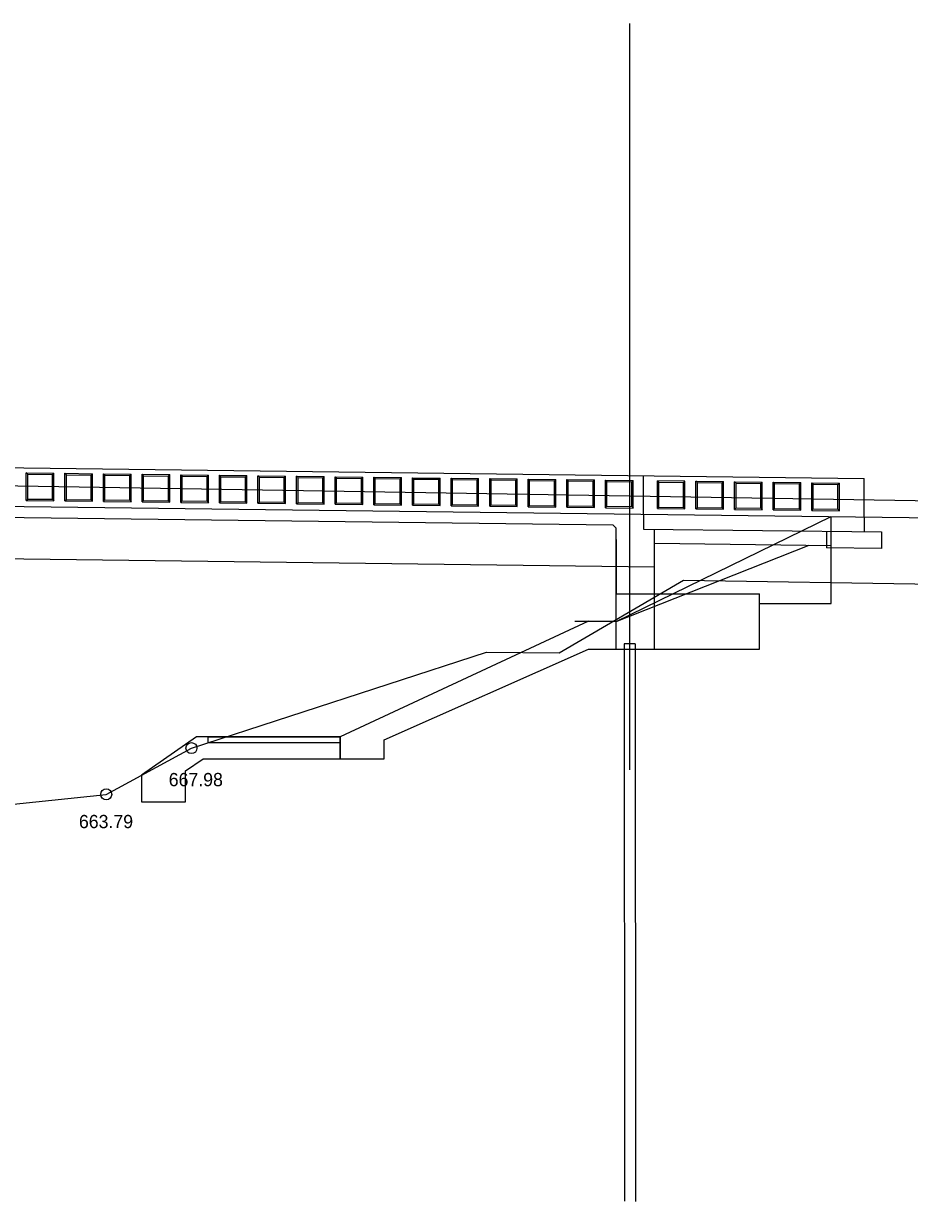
# Model space of a CAD drawing. Extents: x -845213 to 599959, y -257022 to 228999.
# Drawn here: x 595643.5 to 595723.8, y 228653.8 to 228760.5 of the extents above; entities that cross this region are included whole.
import ezdxf

# ---------------------------------------------------------------- set-up
doc = ezdxf.new("R2010")
doc.units = 0
for name, color, linetype in [('B_CL', 7, 'Continuous'), ('B_CONC', 7, 'Continuous'), ('B_CONC_HIDDEN', 7, 'Continuous'), ('B_CONST', 7, 'Continuous'), ('B_GROUNDLINE', 7, 'Continuous'), ('B_MISC', 7, 'Continuous'), ('B_PATTERN', 7, 'Continuous'), ('B_PILES_HIDDEN', 7, 'Continuous'), ('B_PROP', 7, 'Continuous'), ('B_SCREEN', 7, 'Continuous'), ('E_STRUCT', 7, 'Continuous'), ('P_E_PROF', 7, 'Continuous'), ('P_PROF', 7, 'Continuous')]:
    doc.layers.add(name, color=color, linetype=linetype)

msp = doc.modelspace()

# ---------------------------------------------------------------- linework, layer by layer
at = {"layer": 'B_CL'}
for p, q in [((595698.5, 228692.87), (595698.5, 228760.49)), ((595698.5, 228703.82), (595698.5, 228708.82))]:
    msp.add_line(p, q, dxfattribs=at)
at = {"layer": 'B_CONC'}
for p, q in [((595399.25, 228723.31), (595719.75, 228719.29)), ((595699.75, 228716.04), (595699.75, 228719.54)), ((595719.75, 228715.79), (595719.75, 228719.29)), ((595421.62, 228718.53), (595696.95, 228715.07)), ((595716.75, 228707.95), (595716.75, 228715.83)), ((595417.81, 228714.82), (595700.75, 228711.28)), ((595697.25, 228714.77), (595696.95, 228715.07)), ((595697.25, 228703.82), (595697.25, 228714.77)), ((595710.25, 228703.82), (595710.25, 228708.82)), ((595710.25, 228707.95), (595716.75, 228707.95))]:
    msp.add_line(p, q, dxfattribs=at)
at = {"layer": 'B_CONC_HIDDEN'}
msp.add_line((595699.75, 228716.04), (595699.75, 228715.04), dxfattribs=at)
at = {"layer": 'B_CONST'}
for p, q in [((595697.25, 228713.75), (595697.25, 228708.84)), ((595697.25, 228706.51), (595697.25, 228711.51))]:
    msp.add_line(p, q, dxfattribs=at)
at = {"layer": 'B_GROUNDLINE'}
msp.add_lwpolyline([(595697.25, 228706.32), (595716.75, 228715.83)], dxfattribs=at)
at = {"layer": 'B_MISC'}
for p, q in [((595697.25, 228706.32), (595714.75, 228713.23)), ((595700.75, 228703.82), (595700.75, 228713.43)), ((595700.75, 228713.43), (595716.75, 228713.2)), ((595716.75, 228707.95), (595716.75, 228713.2)), ((595697.25, 228703.82), (595697.25, 228708.82)), ((595697.25, 228708.82), (595710.25, 228708.82)), ((595710.25, 228703.82), (595710.25, 228708.82)), ((595710.25, 228707.95), (595716.75, 228707.95)), ((595697.25, 228706.32), (595693.53, 228706.32)), ((595697.25, 228703.82), (595697.25, 228706.42)), ((595697.25, 228703.82), (595710.25, 228703.82))]:
    msp.add_line(p, q, dxfattribs=at)
for centre in [(595658.77, 228694.85), (595651.04, 228690.66)]:
    msp.add_circle(centre, 0.5, dxfattribs=at)
at = {"layer": 'B_PATTERN'}
for points in [[(595697.25, 228703.82), (595697.25, 228706.32), (595694.75, 228706.35), (595672.25, 228695.87), (595672.25, 228693.87), (595676.25, 228693.87), (595676.25, 228695.61), (595694.75, 228703.82)], [(595672.25, 228693.87), (595672.25, 228695.87), (595659.24, 228695.86), (595654.24, 228692.41), (595654.24, 228689.99), (595658.24, 228689.99), (595658.24, 228692.78), (595659.84, 228693.87)]]:
    msp.add_lwpolyline(points, close=True, dxfattribs=at)
at = {"layer": 'B_PILES_HIDDEN'}
for p, q in [((595699, 228704.29), (595698, 228704.31)), ((595698, 228704.31), (595698.02, 228653.8)), ((595699, 228704.29), (595699.02, 228653.78))]:
    msp.add_line(p, q, dxfattribs=at)
at = {"layer": 'B_PROP'}
for p, q in [((595660.25, 228695.87), (595672.25, 228695.87)), ((595660.25, 228695.87), (595660.25, 228695.37)), ((595660.25, 228695.37), (595672.25, 228695.37))]:
    msp.add_line(p, q, dxfattribs=at)
at = {"layer": 'B_SCREEN'}
for p, q in [((595643.8, 228717.29), (595643.8, 228719.79)), ((595643.8, 228719.79), (595646.3, 228719.76)), ((595643.93, 228719.66), (595643.8, 228719.79)), ((595643.93, 228719.66), (595646.18, 228719.64)), ((595643.93, 228717.41), (595643.93, 228719.66)), ((595646.18, 228719.64), (595646.3, 228719.76)), ((595646.18, 228717.39), (595646.18, 228719.64)), ((595646.3, 228717.26), (595646.3, 228719.76)), ((595647.3, 228717.25), (595647.3, 228719.75)), ((595647.3, 228719.75), (595649.8, 228719.71)), ((595647.43, 228719.62), (595647.3, 228719.75)), ((595647.43, 228719.62), (595649.68, 228719.59)), ((595647.43, 228717.37), (595647.43, 228719.62)), ((595649.68, 228719.59), (595649.8, 228719.71)), ((595649.68, 228717.34), (595649.68, 228719.59)), ((595649.8, 228717.21), (595649.8, 228719.71)), ((595650.8, 228717.2), (595650.8, 228719.7)), ((595650.8, 228719.7), (595653.3, 228719.67)), ((595650.93, 228719.58), (595650.8, 228719.7)), ((595650.93, 228719.58), (595653.18, 228719.55)), ((595650.93, 228717.33), (595650.93, 228719.58)), ((595653.18, 228719.55), (595653.3, 228719.67)), ((595653.18, 228717.3), (595653.18, 228719.55)), ((595653.3, 228717.17), (595653.3, 228719.67)), ((595654.3, 228717.16), (595654.3, 228719.66)), ((595654.3, 228719.66), (595656.8, 228719.63)), ((595654.43, 228719.53), (595654.3, 228719.66)), ((595654.43, 228719.53), (595656.68, 228719.5)), ((595654.43, 228717.28), (595654.43, 228719.53)), ((595656.68, 228719.5), (595656.8, 228719.63)), ((595656.68, 228717.25), (595656.68, 228719.5)), ((595656.8, 228717.13), (595656.8, 228719.63)), ((595657.8, 228717.11), (595657.8, 228719.61)), ((595657.8, 228719.61), (595660.3, 228719.58)), ((595657.93, 228719.49), (595657.8, 228719.61)), ((595657.93, 228719.49), (595660.18, 228719.46)), ((595657.93, 228717.24), (595657.93, 228719.49)), ((595660.18, 228719.46), (595660.3, 228719.58)), ((595660.18, 228717.21), (595660.18, 228719.46)), ((595660.3, 228717.08), (595660.3, 228719.58)), ((595661.3, 228717.07), (595661.3, 228719.57)), ((595661.3, 228719.57), (595663.8, 228719.54)), ((595661.43, 228719.44), (595661.3, 228719.57)), ((595661.43, 228719.44), (595663.68, 228719.42)), ((595661.43, 228717.19), (595661.43, 228719.44)), ((595663.68, 228719.42), (595663.8, 228719.54)), ((595663.68, 228717.17), (595663.68, 228719.42)), ((595663.8, 228717.04), (595663.8, 228719.54)), ((595664.8, 228717.03), (595664.8, 228719.53)), ((595664.8, 228719.53), (595667.3, 228719.5)), ((595664.93, 228719.4), (595664.8, 228719.53)), ((595664.93, 228719.4), (595667.18, 228719.37)), ((595664.93, 228717.15), (595664.93, 228719.4)), ((595667.18, 228719.37), (595667.3, 228719.5)), ((595667.18, 228717.12), (595667.18, 228719.37)), ((595667.3, 228717), (595667.3, 228719.5)), ((595668.3, 228716.98), (595668.3, 228719.48)), ((595668.3, 228719.48), (595670.8, 228719.45)), ((595668.43, 228719.36), (595668.3, 228719.48)), ((595668.43, 228719.36), (595670.68, 228719.33)), ((595668.43, 228717.11), (595668.43, 228719.36)), ((595670.68, 228719.33), (595670.8, 228719.45)), ((595670.68, 228717.08), (595670.68, 228719.33)), ((595670.8, 228716.95), (595670.8, 228719.45)), ((595671.8, 228716.94), (595671.8, 228719.44)), ((595671.8, 228719.44), (595674.3, 228719.41)), ((595671.93, 228719.31), (595671.8, 228719.44)), ((595671.93, 228719.31), (595674.18, 228719.28)), ((595671.93, 228717.06), (595671.93, 228719.31)), ((595674.18, 228719.28), (595674.3, 228719.41)), ((595674.18, 228717.03), (595674.18, 228719.28)), ((595674.3, 228716.91), (595674.3, 228719.41)), ((595675.3, 228716.9), (595675.3, 228719.39)), ((595675.3, 228719.39), (595677.8, 228719.36)), ((595675.43, 228719.27), (595675.3, 228719.39)), ((595675.43, 228719.27), (595677.68, 228719.24)), ((595675.43, 228717.02), (595675.43, 228719.27)), ((595677.68, 228719.24), (595677.8, 228719.36)), ((595677.68, 228716.99), (595677.68, 228719.24)), ((595677.8, 228716.86), (595677.8, 228719.36)), ((595678.8, 228716.85), (595678.8, 228719.35)), ((595678.8, 228719.35), (595681.3, 228719.32)), ((595678.93, 228719.22), (595678.8, 228719.35)), ((595678.93, 228719.22), (595681.18, 228719.2)), ((595678.93, 228716.97), (595678.93, 228719.22)), ((595681.18, 228719.2), (595681.3, 228719.32)), ((595681.18, 228716.95), (595681.18, 228719.2)), ((595681.3, 228716.82), (595681.3, 228719.32)), ((595682.3, 228716.81), (595682.3, 228719.31)), ((595682.3, 228719.31), (595684.8, 228719.28)), ((595682.43, 228719.18), (595682.3, 228719.31)), ((595682.43, 228719.18), (595684.67, 228719.15)), ((595682.43, 228716.93), (595682.43, 228719.18)), ((595684.67, 228719.15), (595684.8, 228719.28)), ((595684.67, 228716.9), (595684.67, 228719.15)), ((595684.8, 228716.78), (595684.8, 228719.28)), ((595685.8, 228716.76), (595685.8, 228719.26)), ((595685.8, 228719.26), (595688.3, 228719.23)), ((595685.92, 228719.14), (595685.8, 228719.26)), ((595685.92, 228719.14), (595688.17, 228719.11)), ((595685.92, 228716.89), (595685.92, 228719.14)), ((595688.17, 228719.11), (595688.3, 228719.23)), ((595688.17, 228716.86), (595688.17, 228719.11)), ((595688.3, 228716.73), (595688.3, 228719.23)), ((595689.3, 228716.72), (595689.3, 228719.22)), ((595689.3, 228719.22), (595691.8, 228719.19)), ((595689.42, 228719.09), (595689.3, 228719.22)), ((595689.42, 228719.09), (595691.67, 228719.06)), ((595689.42, 228716.84), (595689.42, 228719.09)), ((595691.67, 228719.06), (595691.8, 228719.19)), ((595691.67, 228716.81), (595691.67, 228719.06)), ((595691.8, 228716.69), (595691.8, 228719.19)), ((595692.8, 228716.68), (595692.8, 228719.18)), ((595692.8, 228719.18), (595695.3, 228719.14)), ((595692.92, 228719.05), (595692.8, 228719.18)), ((595692.92, 228719.05), (595695.17, 228719.02)), ((595692.92, 228716.8), (595692.92, 228719.05)), ((595695.17, 228719.02), (595695.3, 228719.14)), ((595695.17, 228716.77), (595695.17, 228719.02)), ((595695.3, 228716.64), (595695.3, 228719.14)), ((595696.3, 228716.63), (595696.3, 228719.13)), ((595696.3, 228719.13), (595698.8, 228719.1)), ((595696.42, 228719.01), (595696.3, 228719.13)), ((595696.42, 228719.01), (595698.67, 228718.98)), ((595696.42, 228716.76), (595696.42, 228719.01)), ((595698.67, 228718.98), (595698.8, 228719.1)), ((595698.67, 228716.73), (595698.67, 228718.98)), ((595698.8, 228716.6), (595698.8, 228719.1)), ((595703.5, 228719.04), (595701, 228719.07)), ((595701, 228716.57), (595701, 228719.07)), ((595701.13, 228718.94), (595701, 228719.07)), ((595701.13, 228718.94), (595703.38, 228718.91)), ((595701.13, 228716.69), (595701.13, 228718.94)), ((595703.38, 228718.91), (595703.5, 228719.04)), ((595703.38, 228716.66), (595703.38, 228718.91)), ((595703.5, 228716.54), (595703.5, 228719.04)), ((595704.5, 228716.53), (595704.5, 228719.03)), ((595704.5, 228719.03), (595707, 228718.99)), ((595704.63, 228718.9), (595704.5, 228719.03)), ((595704.63, 228718.9), (595706.88, 228718.87)), ((595704.63, 228716.65), (595704.63, 228718.9)), ((595706.88, 228718.87), (595707, 228718.99)), ((595707, 228716.49), (595707, 228718.99)), ((595708, 228716.48), (595708, 228718.98)), ((595708, 228718.98), (595710.5, 228718.95)), ((595708.13, 228718.86), (595708, 228718.98)), ((595710.38, 228718.83), (595710.5, 228718.95)), ((595710.5, 228716.45), (595710.5, 228718.95)), ((595711.5, 228716.44), (595711.5, 228718.94)), ((595711.5, 228718.94), (595714, 228718.91)), ((595711.63, 228718.81), (595711.5, 228718.94)), ((595713.87, 228718.78), (595714, 228718.91)), ((595714, 228716.41), (595714, 228718.91)), ((595715, 228716.39), (595715, 228718.89)), ((595715, 228718.89), (595717.5, 228718.86)), ((595715.12, 228718.77), (595715, 228718.89)), ((595706.88, 228716.62), (595706.88, 228718.87)), ((595708.13, 228718.86), (595710.38, 228718.83)), ((595708.13, 228716.61), (595708.13, 228718.86)), ((595710.38, 228716.58), (595710.38, 228718.83)), ((595711.63, 228718.81), (595713.87, 228718.78)), ((595711.63, 228716.56), (595711.63, 228718.81)), ((595713.87, 228716.53), (595713.87, 228718.78)), ((595715.12, 228718.77), (595717.37, 228718.74)), ((595715.12, 228716.52), (595715.12, 228718.77)), ((595717.37, 228718.74), (595717.5, 228718.86)), ((595717.37, 228716.49), (595717.37, 228718.74)), ((595717.5, 228716.36), (595717.5, 228718.86)), ((595643.8, 228717.29), (595643.93, 228717.41)), ((595643.8, 228717.29), (595646.3, 228717.26)), ((595643.93, 228717.41), (595646.18, 228717.39)), ((595646.18, 228717.39), (595646.3, 228717.26)), ((595647.3, 228717.25), (595647.43, 228717.37)), ((595647.3, 228717.25), (595649.8, 228717.21)), ((595647.43, 228717.37), (595649.68, 228717.34)), ((595649.68, 228717.34), (595649.8, 228717.21)), ((595650.8, 228717.2), (595650.93, 228717.33)), ((595650.8, 228717.2), (595653.3, 228717.17)), ((595650.93, 228717.33), (595653.18, 228717.3)), ((595653.18, 228717.3), (595653.3, 228717.17)), ((595654.3, 228717.16), (595654.43, 228717.28)), ((595654.3, 228717.16), (595656.8, 228717.13)), ((595654.43, 228717.28), (595656.68, 228717.25)), ((595656.68, 228717.25), (595656.8, 228717.13)), ((595657.8, 228717.11), (595657.93, 228717.24)), ((595657.8, 228717.11), (595660.3, 228717.08)), ((595657.93, 228717.24), (595660.18, 228717.21)), ((595660.18, 228717.21), (595660.3, 228717.08)), ((595661.3, 228717.07), (595661.43, 228717.19)), ((595661.3, 228717.07), (595663.8, 228717.04)), ((595661.43, 228717.19), (595663.68, 228717.17)), ((595663.68, 228717.17), (595663.8, 228717.04)), ((595664.8, 228717.03), (595664.93, 228717.15)), ((595664.8, 228717.03), (595667.3, 228717)), ((595664.93, 228717.15), (595667.18, 228717.12)), ((595667.18, 228717.12), (595667.3, 228717)), ((595668.3, 228716.98), (595668.43, 228717.11)), ((595668.3, 228716.98), (595670.8, 228716.95)), ((595668.43, 228717.11), (595670.68, 228717.08)), ((595670.68, 228717.08), (595670.8, 228716.95)), ((595671.8, 228716.94), (595671.93, 228717.06)), ((595671.8, 228716.94), (595674.3, 228716.91)), ((595671.93, 228717.06), (595674.18, 228717.03)), ((595674.18, 228717.03), (595674.3, 228716.91)), ((595675.3, 228716.9), (595675.43, 228717.02)), ((595675.3, 228716.9), (595677.8, 228716.86)), ((595675.43, 228717.02), (595677.68, 228716.99)), ((595677.68, 228716.99), (595677.8, 228716.86)), ((595678.8, 228716.85), (595678.93, 228716.97)), ((595678.8, 228716.85), (595681.3, 228716.82)), ((595678.93, 228716.97), (595681.18, 228716.95)), ((595681.18, 228716.95), (595681.3, 228716.82)), ((595682.3, 228716.81), (595682.43, 228716.93)), ((595682.3, 228716.81), (595684.8, 228716.78)), ((595682.43, 228716.93), (595684.67, 228716.9)), ((595684.67, 228716.9), (595684.8, 228716.78)), ((595685.8, 228716.76), (595685.92, 228716.89)), ((595685.8, 228716.76), (595688.3, 228716.73)), ((595685.92, 228716.89), (595688.17, 228716.86)), ((595688.17, 228716.86), (595688.3, 228716.73)), ((595689.3, 228716.72), (595689.42, 228716.84)), ((595689.42, 228716.84), (595691.67, 228716.81)), ((595691.67, 228716.81), (595691.8, 228716.69)), ((595692.8, 228716.68), (595692.92, 228716.8)), ((595692.92, 228716.8), (595695.17, 228716.77)), ((595695.17, 228716.77), (595695.3, 228716.64)), ((595696.3, 228716.63), (595696.42, 228716.76)), ((595696.42, 228716.76), (595698.67, 228716.73)), ((595689.3, 228716.72), (595691.8, 228716.69)), ((595692.8, 228716.68), (595695.3, 228716.64)), ((595696.3, 228716.63), (595698.8, 228716.6)), ((595698.67, 228716.73), (595698.8, 228716.6)), ((595701, 228716.57), (595701.13, 228716.69)), ((595701, 228716.57), (595703.5, 228716.54)), ((595701.13, 228716.69), (595703.38, 228716.66)), ((595703.38, 228716.66), (595703.5, 228716.54)), ((595704.5, 228716.53), (595704.63, 228716.65)), ((595704.5, 228716.53), (595707, 228716.49)), ((595704.63, 228716.65), (595706.88, 228716.62)), ((595706.88, 228716.62), (595707, 228716.49)), ((595708, 228716.48), (595708.13, 228716.61)), ((595708, 228716.48), (595710.5, 228716.45)), ((595708.13, 228716.61), (595710.38, 228716.58)), ((595710.38, 228716.58), (595710.5, 228716.45)), ((595711.5, 228716.44), (595711.63, 228716.56)), ((595711.5, 228716.44), (595714, 228716.41)), ((595711.63, 228716.56), (595713.87, 228716.53)), ((595713.87, 228716.53), (595714, 228716.41)), ((595715, 228716.39), (595715.12, 228716.52)), ((595715, 228716.39), (595717.5, 228716.36)), ((595715.12, 228716.52), (595717.37, 228716.49)), ((595717.37, 228716.49), (595717.5, 228716.36))]:
    msp.add_line(p, q, dxfattribs=at)
at = {"layer": 'E_STRUCT'}
msp.add_line((595399.35, 228722.55), (595731.51, 228717.17), dxfattribs=at)
at = {"layer": 'P_E_PROF'}
for p, q in [((595692.09, 228703.47), (595703.38, 228710.07)), ((595703.38, 228710.07), (595793.02, 228708.6)), ((595658.77, 228694.85), (595685.51, 228703.55)), ((595685.51, 228703.55), (595692.09, 228703.47)), ((595651.04, 228690.66), (595658.77, 228694.85)), ((595640.72, 228689.56), (595651.04, 228690.66))]:
    msp.add_line(p, q, dxfattribs=at)
at = {"layer": 'P_PROF'}
for p, q in [((595315.56, 228720.86), (595815.56, 228714.59)), ((595699.75, 228716.04), (595699.75, 228714.7)), ((595719.75, 228715.79), (595719.75, 228714.45)), ((595699.75, 228714.7), (595721.32, 228714.43)), ((595700.75, 228703.78), (595700.75, 228714.69)), ((595716.32, 228714.5), (595716.32, 228713)), ((595721.32, 228714.43), (595721.32, 228712.93)), ((595721.32, 228712.93), (595716.32, 228713)), ((595700.75, 228708.82), (595710.25, 228708.82)), ((595697.25, 228703.82), (595710.25, 228703.82))]:
    msp.add_line(p, q, dxfattribs=at)

# ---------------------------------------------------------------- texts
at = {"layer": 'B_MISC'}
for s, p in [('667.98', (595656.71, 228691.4)), ('663.79', (595648.57, 228687.6))]:
    msp.add_text(s, height=1.2, dxfattribs=at).set_placement(p)

doc.saveas('drawing.dxf')
